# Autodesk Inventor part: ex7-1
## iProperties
Shininess: 64.0
Length Units: 11272
Angle Units: 11279
Time Units: 11290
Mass Units: 11286
Length Display Precision: 3
Angle Display Precision: 2
Compacted: True
Part Number: ex7-1
Document SubType Name: Modeling
Created: 2002-11
Designer: Elise Moss
Density: 0.0
Volumn: 0.0
Area: 0.0
PropertySet Name: Model Information
Control State: 0
Master: False
Checked Out: False
Author: Elise Moss
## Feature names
1. Hole1
2. Hole2
3. Base1
